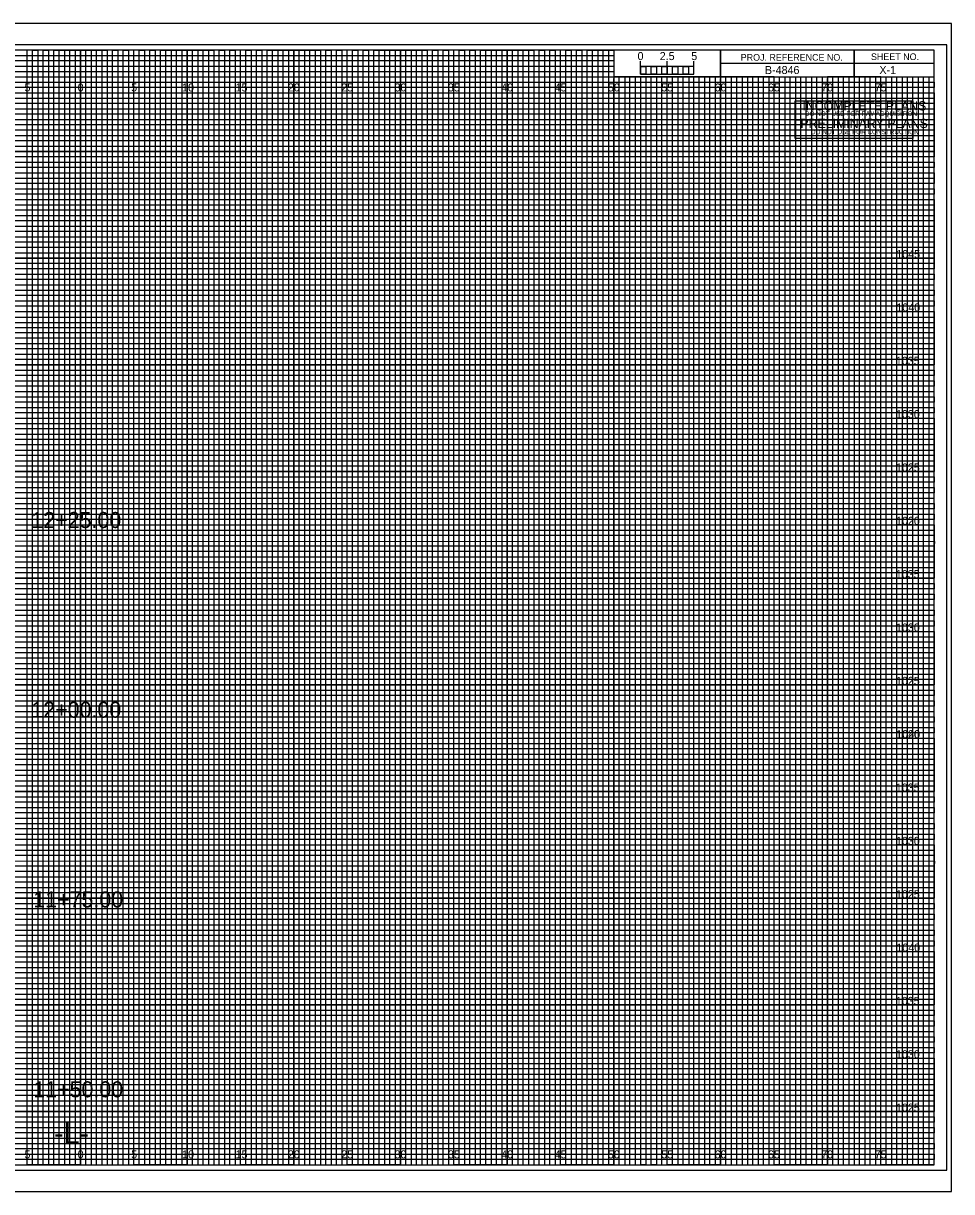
# Model space of a CAD drawing. Extents: x -7 to 162, y -2 to 987.
# Drawn here: x 74.6 to 161.7, y -2.5 to 107 of the extents above; entities that cross this region are included whole.
import ezdxf

# ---------------------------------------------------------------- set-up
doc = ezdxf.new("R2010")
doc.units = 0
for name, color, linetype in [('Default', 7, 'Continuous'), ('Exist Cross Section Cell', 7, 'Continuous'), ('Exist XS Center Line Elevation Label', 7, 'Continuous'), ('Exist XS Ground Line', 7, 'Continuous'), ('Prop CMT Concrete Structures', 7, 'Continuous'), ('Prop CMT DNC', 7, 'Continuous'), ('Prop CMT Guardrail Graphics', 7, 'Continuous'), ('Prop CMT Guardrail Widen Shoulder', 7, 'Continuous'), ('Prop CMT Pvmt Course 1', 7, 'Continuous'), ('Prop CMT Pvmt Surface', 7, 'Continuous'), ('Prop CMT Pvmt Surface Shoulder', 7, 'Continuous'), ('Prop CMT Shld Paved Course 1', 7, 'Continuous'), ('Prop CMT Shoulder Point', 7, 'Continuous'), ('Prop CMT Slope Grass', 7, 'Continuous'), ('Prop CMT Subgrade Earthwork', 7, 'Continuous'), ('Prop XS SE Text', 7, 'Continuous'), ('Prop XS Side Slope Text', 7, 'Continuous'), ('Typical Text Label CELL', 7, 'Continuous')]:
    doc.layers.add(name, color=color, linetype=linetype)

msp = doc.modelspace()

# ---------------------------------------------------------------- linework, layer by layer
at = {"layer": 'Default'}
for points in [[(146.99, 97.97), (146.99, 99.73), (158.01, 99.73), (158.01, 97.97)], [(146.99, 96.2), (146.99, 97.97), (158.01, 97.97), (158.01, 96.2)]]:
    msp.add_lwpolyline(points, close=True, dxfattribs=at)
at = {"layer": 'Exist XS Center Line Elevation Label'}
for points in [[(72.5, 0), (77.5, 0), (77.5, 104.5), (82.5, 104.5), (82.5, 0), (87.5, 0), (87.5, 104.5), (92.5, 104.5), (92.5, 0), (97.5, 0), (97.5, 104.5), (102.5, 104.5), (102.5, 0), (107.5, 0), (107.5, 104.5), (112.5, 104.5), (112.5, 0), (117.5, 0), (117.5, 104.5), (122.5, 104.5), (122.5, 0), (127.5, 0), (127.5, 104.5), (129.97, 104.5), (130, 104.5), (130, 102), (132.5, 102), (132.5, 0), (137.5, 0), (137.5, 102), (142.5, 102), (142.5, 0), (147.5, 0), (147.5, 102), (152.5, 102), (152.5, 0), (157.5, 0), (157.5, 102)], [(0, 102), (137.5, 102)], [(0, 92.5), (160, 92.5), (160, 97.5), (0, 97.5)], [(0, 82.5), (160, 82.5), (160, 87.5), (0, 87.5)], [(0, 72.5), (160, 72.5), (160, 77.5), (0, 77.5)], [(0, 62.5), (160, 62.5), (160, 67.5), (0, 67.5)], [(0, 52.5), (160, 52.5), (160, 57.5), (0, 57.5)], [(0, 42.5), (160, 42.5), (160, 47.5), (0, 47.5)], [(0, 32.5), (160, 32.5), (160, 37.5), (0, 37.5)], [(0, 22.5), (160, 22.5), (160, 27.5), (0, 27.5)], [(0, 12.5), (160, 12.5), (160, 17.5), (0, 17.5)], [(0, 2.5), (160, 2.5), (160, 7.5), (0, 7.5)]]:
    msp.add_lwpolyline(points, dxfattribs=at)
at = {"layer": 'Exist XS Ground Line'}
for p, q in [((75, 104.5), (70, 104.5)), ((75, 0), (75, 104.5)), ((85, 104.5), (80, 104.5)), ((80, 104.5), (80, 0)), ((85, 0), (85, 104.5)), ((95, 104.5), (90, 104.5)), ((90, 104.5), (90, 0)), ((95, 0), (95, 104.5)), ((105, 104.5), (100, 104.5)), ((100, 104.5), (100, 0)), ((105, 0), (105, 104.5)), ((115, 104.5), (110, 104.5)), ((110, 104.5), (110, 0)), ((115, 0), (115, 104.5)), ((125, 104.5), (120, 104.5)), ((120, 104.5), (120, 0)), ((125, 0), (125, 104.5)), ((130, 104.5), (130, 0)), ((135, 0), (135, 102)), ((145, 102), (140, 102)), ((140, 102), (140, 0)), ((145, 0), (145, 102)), ((155, 102), (150, 102)), ((150, 102), (150, 0)), ((155, 0), (155, 102)), ((80, 0), (75, 0)), ((90, 0), (85, 0)), ((100, 0), (95, 0)), ((110, 0), (105, 0)), ((120, 0), (115, 0)), ((130, 0), (125, 0)), ((140, 0), (135, 0)), ((150, 0), (145, 0)), ((160, 0), (155, 0)), ((160, 0), (160, 0))]:
    msp.add_line(p, q, dxfattribs=at)
for points in [[(0, 100), (160, 100), (160, 95), (0, 95)], [(0, 90), (160, 90), (160, 85), (0, 85)], [(0, 80), (160, 80), (160, 75), (0, 75)], [(0, 70), (160, 70), (160, 65), (0, 65)], [(0, 60), (160, 60), (160, 55), (0, 55)], [(0, 50), (160, 50), (160, 45), (0, 45)], [(0, 40), (160, 40), (160, 35), (0, 35)], [(0, 30), (160, 30), (160, 25), (0, 25)], [(0, 20), (160, 20), (160, 15), (0, 15)], [(0, 10), (160, 10), (160, 5), (0, 5)]]:
    msp.add_lwpolyline(points, dxfattribs=at)
at = {"layer": 'Prop CMT Concrete Structures'}
for p, q in [((75, 0), (75, 104.5)), ((80, 0), (80, 104.5)), ((85, 0), (85, 104.5)), ((90, 0), (90, 104.5)), ((95, 0), (95, 104.5)), ((100, 0), (100, 104.5)), ((105, 0), (105, 104.5)), ((110, 0), (110, 104.5)), ((115, 0), (115, 104.5)), ((120, 0), (120, 104.5)), ((125, 0), (125, 104.5)), ((130, 0), (130, 101.84)), ((135, 0), (135, 101.84)), ((140, 0), (140, 101.84)), ((145, 0), (145, 101.84)), ((150, 0), (150, 101.84)), ((155, 0), (155, 101.84)), ((0, 100), (160, 100)), ((0, 95), (160, 95)), ((0, 90), (160, 90)), ((0, 85), (160, 85)), ((0, 80), (160, 80)), ((0, 75), (160, 75)), ((0, 70), (160, 70)), ((0, 65), (160, 65)), ((0, 60), (160, 60)), ((0, 55), (160, 55)), ((0, 50), (160, 50)), ((0, 45), (160, 45)), ((0, 40), (160, 40)), ((0, 35), (160, 35)), ((0, 30), (160, 30)), ((0, 25), (160, 25)), ((0, 20), (160, 20)), ((0, 15), (160, 15)), ((0, 10), (160, 10)), ((0, 5), (160, 5))]:
    msp.add_line(p, q, dxfattribs=at)
at = {"layer": 'Prop CMT Guardrail Widen Shoulder'}
for p, q in [((161.65, 107), (-6.7, 107)), ((-6.7, -2.5), (161.65, -2.5))]:
    msp.add_line(p, q, dxfattribs=at)
at = {"layer": 'Prop CMT Pvmt Course 1'}
msp.add_lwpolyline([(-6.7, -2.5), (161.65, -2.5), (161.65, 107), (-6.7, 107)], close=True, dxfattribs=at)
at = {"layer": 'Prop CMT Pvmt Surface'}
for p, q in [((133.5, 102), (133, 102)), ((133, 102), (133, 0)), ((133.5, 0), (133.5, 102)), ((134.5, 102), (134, 102)), ((134, 102), (134, 0)), ((134.5, 0), (134.5, 102)), ((133, 0), (132.5, 0)), ((134, 0), (133.5, 0))]:
    msp.add_line(p, q, dxfattribs=at)
for points in [[(75, 0), (75.5, 0), (75.5, 104.5), (76, 104.5), (76, 0)], [(76, 0), (76.5, 0), (76.5, 104.5), (77, 104.5), (77, 0)], [(77.5, 0), (78, 0), (78, 104.5), (78.5, 104.5), (78.5, 0)], [(78.5, 0), (79, 0), (79, 104.5), (79.5, 104.5), (79.5, 0)], [(80, 0), (80.5, 0), (80.5, 104.5), (81, 104.5), (81, 0)], [(81, 0), (81.5, 0), (81.5, 104.5), (82, 104.5), (82, 0)], [(82.5, 0), (83, 0), (83, 104.5), (83.5, 104.5), (83.5, 0)], [(83.5, 0), (84, 0), (84, 104.5), (84.5, 104.5), (84.5, 0)], [(85, 0), (85.5, 0), (85.5, 104.5), (86, 104.5), (86, 0)], [(86, 0), (86.5, 0), (86.5, 104.5), (87, 104.5), (87, 0)], [(87.5, 0), (88, 0), (88, 104.5), (88.5, 104.5), (88.5, 0)], [(88.5, 0), (89, 0), (89, 104.5), (89.5, 104.5), (89.5, 0)], [(90, 0), (90.5, 0), (90.5, 104.5), (91, 104.5), (91, 0)], [(91, 0), (91.5, 0), (91.5, 104.5), (92, 104.5), (92, 0)], [(92.5, 0), (93, 0), (93, 104.5), (93.5, 104.5), (93.5, 0)], [(93.5, 0), (94, 0), (94, 104.5), (94.5, 104.5), (94.5, 0)], [(95, 0), (95.5, 0), (95.5, 104.5), (96, 104.5), (96, 0)], [(96, 0), (96.5, 0), (96.5, 104.5), (97, 104.5), (97, 0)], [(97.5, 0), (98, 0), (98, 104.5), (98.5, 104.5), (98.5, 0)], [(98.5, 0), (99, 0), (99, 104.5), (99.5, 104.5), (99.5, 0)], [(100, 0), (100.5, 0), (100.5, 104.5), (101, 104.5), (101, 0)], [(101, 0), (101.5, 0), (101.5, 104.5), (102, 104.5), (102, 0)], [(102.5, 0), (103, 0), (103, 104.5), (103.5, 104.5), (103.5, 0)], [(103.5, 0), (104, 0), (104, 104.5), (104.5, 104.5), (104.5, 0)], [(105, 0), (105.5, 0), (105.5, 104.5), (106, 104.5), (106, 0)], [(106, 0), (106.5, 0), (106.5, 104.5), (107, 104.5), (107, 0)], [(107.5, 0), (108, 0), (108, 104.5), (108.5, 104.5), (108.5, 0)], [(108.5, 0), (109, 0), (109, 104.5), (109.5, 104.5), (109.5, 0)], [(110, 0), (110.5, 0), (110.5, 104.5), (111, 104.5), (111, 0)], [(111, 0), (111.5, 0), (111.5, 104.5), (112, 104.5), (112, 0)], [(112.5, 0), (113, 0), (113, 104.5), (113.5, 104.5), (113.5, 0)], [(113.5, 0), (114, 0), (114, 104.5), (114.5, 104.5), (114.5, 0)], [(115, 0), (115.5, 0), (115.5, 104.5), (116, 104.5), (116, 0)], [(116, 0), (116.5, 0), (116.5, 104.5), (117, 104.5), (117, 0)], [(117.5, 0), (118, 0), (118, 104.5), (118.5, 104.5), (118.5, 0)], [(118.5, 0), (119, 0), (119, 104.5), (119.5, 104.5), (119.5, 0)], [(120, 0), (120.5, 0), (120.5, 104.5), (121, 104.5), (121, 0)], [(121, 0), (121.5, 0), (121.5, 104.5), (122, 104.5), (122, 0)], [(122.5, 0), (123, 0), (123, 104.5), (123.5, 104.5), (123.5, 0)], [(123.5, 0), (124, 0), (124, 104.5), (124.5, 104.5), (124.5, 0)], [(125, 0), (125.5, 0), (125.5, 104.5), (126, 104.5), (126, 0)], [(126, 0), (126.5, 0), (126.5, 104.5), (127, 104.5), (127, 0)], [(127.5, 0), (128, 0), (128, 104.5), (128.5, 104.5), (128.5, 0)], [(128.5, 0), (129, 0), (129, 104.5), (129.5, 104.5), (129.5, 0)], [(130, 0), (130.5, 0), (130.5, 102), (131.01, 102), (131.01, 0)], [(131, 0), (131.5, 0), (131.5, 102), (132, 102), (132, 0)], [(135, 0), (135.49, 0), (135.49, 102), (136, 102), (136, 0)], [(136, 0), (136.5, 0), (136.5, 102), (137.03, 102), (137.03, 0)], [(137.5, 0), (138, 0), (138, 102), (138.5, 102), (138.5, 0)], [(138.5, 0), (139, 0), (139, 102), (139.5, 102), (139.5, 0)], [(140, 0), (140.5, 0), (140.5, 102), (141, 102), (141, 0)], [(141, 0), (141.5, 0), (141.5, 102), (142, 102), (142, 0)], [(142.5, 0), (143, 0), (143, 102), (143.5, 102), (143.5, 0)], [(143.5, 0), (144, 0), (144, 102), (144.5, 102), (144.5, 0)], [(145, 0), (145.5, 0), (145.5, 102), (146, 102), (146, 0)], [(146, 0), (146.5, 0), (146.5, 102), (147, 102), (147, 0)], [(147.5, 0), (148, 0), (148, 102), (148.5, 102), (148.5, 0)], [(148.5, 0), (149, 0), (149, 102), (149.5, 102), (149.5, 0)], [(150, 0), (150.5, 0), (150.5, 102), (151, 102), (151, 0)], [(151, 0), (151.5, 0), (151.5, 102), (152, 102), (152, 0)], [(152.5, 0), (153, 0), (153, 102), (153.5, 102), (153.5, 0)], [(153.5, 0), (154, 0), (154, 102), (154.5, 102), (154.5, 0)], [(155, 0), (155.5, 0), (155.5, 102), (156, 102), (156, 0)], [(156, 0), (156.5, 0), (156.5, 102), (157, 102), (157, 0)], [(157.5, 0), (158, 0), (158, 102), (158.5, 102), (158.5, 0)], [(158.5, 0), (159, 0), (159, 102), (159.5, 102), (159.5, 0)]]:
    msp.add_lwpolyline(points, dxfattribs=at)
at = {"layer": 'Prop CMT Pvmt Surface Shoulder'}
for p, q in [((132.5, 102.25), (132.5, 103.45)), ((132.5, 102.95), (132.5, 103.45)), ((135, 102.25), (135, 103.45)), ((137.5, 102.25), (137.5, 103.45)), ((137.5, 102.95), (137.5, 103.45))]:
    msp.add_line(p, q, dxfattribs=at)
for points in [[(137.5, 102.95), (132.5, 102.95), (132.5, 102.25), (137.5, 102.25)], [(132.5, 102.95), (133, 102.95), (133, 102.25), (132.5, 102.25)], [(133.5, 102.95), (134, 102.95), (134, 102.25), (133.5, 102.25)], [(134.5, 102.95), (135, 102.95), (135, 102.25), (134.5, 102.25)], [(135.5, 102.95), (136, 102.95), (136, 102.25), (135.5, 102.25)], [(136.5, 102.95), (137, 102.95), (137, 102.25), (136.5, 102.25)]]:
    msp.add_lwpolyline(points, close=True, dxfattribs=at)
at = {"layer": 'Prop CMT Shld Paved Course 1'}
for p, q in [((0, 104), (130, 104)), ((130, 103.49), (0, 103.49)), ((0, 103), (130, 103)), ((130, 104), (130, 103.49)), ((130, 103), (130, 102.45)), ((130, 102.45), (0, 102.45)), ((0, 102), (160, 102))]:
    msp.add_line(p, q, dxfattribs=at)
for points in [[(0, 101.5), (135, 101.5), (160, 101.5), (160, 101), (0, 101)], [(0, 100.5), (160, 100.5), (160, 99.5), (0, 99.5)], [(0, 99), (160, 99), (160, 98.5), (0, 98.49)], [(0, 98), (160, 98), (160, 97), (0, 97)], [(0, 96.5), (160, 96.5), (160, 96), (0, 96)], [(0, 95.5), (160, 95.5), (160, 94.5), (0, 94.5)], [(0, 94), (160, 94), (160, 93.5), (0, 93.5)], [(0, 93), (160, 93), (160, 92), (0, 92)], [(0, 91.5), (160, 91.5), (160, 91), (0, 91)], [(0, 90.5), (160, 90.5), (160, 89.5), (0, 89.5)], [(0, 89), (160, 89), (160, 88.5), (0, 88.5)], [(0, 88), (160, 88), (160, 86.98), (160, 86.5), (160, 86), (0, 86)], [(0, 87), (160, 87), (160, 86.5), (0, 86.5)], [(0, 85.5), (160, 85.5), (160, 84.5), (0, 84.52)], [(0, 84.52), (160, 84.5), (160, 84), (0, 84)], [(0, 83.5), (160, 83.5), (160, 83), (0, 83)], [(0, 82), (160, 82), (160, 81.5), (0, 81.5)], [(0, 81), (160, 81), (160, 80.5), (0, 80.5)], [(-0.04, 79.45), (160, 79.45), (160, 78.94), (-0.04, 78.94)], [(0, 78.5), (160, 78.5), (160, 78), (0, 78)], [(0, 77), (160, 77), (160, 76.5), (0, 76.5)], [(0, 76), (160, 76), (160, 75.5), (0, 75.5)], [(0, 74.5), (160, 74.5), (160, 74), (0, 74)], [(0, 73.5), (160, 73.5), (160, 73), (0, 73)], [(0, 72), (160, 72), (160, 71.5), (0, 71.5)], [(0, 71), (160, 71), (160, 70.5), (0, 70.5)], [(0, 69.5), (160, 69.5), (160, 68.99), (0, 69)], [(0, 68.5), (160, 68.5), (160, 68), (0, 68)], [(0, 67), (160, 67), (160, 66.5), (0, 66.5)], [(0, 66), (160, 66), (160, 65.5), (0, 65.5)], [(0, 64.5), (160, 64.5), (160, 64), (0, 64)], [(0, 63.5), (160, 63.5), (160, 63), (0, 63)], [(0, 62), (160, 62), (160, 61.5), (0, 61.5)], [(0, 61), (160, 61), (160, 60.5), (0, 60.5)], [(0, 59.5), (160, 59.5), (160, 59), (0, 59)], [(0, 58.5), (160.03, 58.45), (160, 58), (0, 58)], [(0, 57), (160, 57), (160, 56.5), (0, 56.5)], [(0, 56), (160, 56), (160, 55.5), (0, 55.5)], [(0, 54.5), (160, 54.5), (160, 54), (0, 54)], [(0, 53.5), (160, 53.5), (160, 53), (0, 53)], [(0, 52), (160, 52), (160, 51.5), (0, 51.5)], [(0, 51), (160, 51), (160, 50.5), (0, 50.5)], [(0, 49.5), (160, 49.5), (160, 49), (0, 49)], [(0, 48.5), (160, 48.5), (160, 48), (0, 48)], [(0, 47), (160, 47), (160, 46.5), (0, 46.5)], [(0, 46), (160, 46), (160, 45.5), (0, 45.5)], [(0, 44.5), (160, 44.5), (160, 44), (0, 44)], [(0, 43.5), (160, 43.5), (160, 43), (0, 43)], [(0, 42), (160, 42), (160, 41.5), (0, 41.5)], [(0, 41), (160, 41), (160, 40.5), (0, 40.5)], [(0, 39.5), (160, 39.5), (160, 38.99), (0, 39)], [(0, 38.5), (160, 38.5), (160, 38), (0, 38)], [(0, 37), (160, 37), (160, 36.5), (0, 36.5)], [(0, 36), (160, 36), (160, 35.5), (0, 35.5)], [(0, 34.5), (160, 34.5), (160, 34), (0, 34)], [(0, 33.5), (160, 33.5), (160, 33), (0, 33)], [(0, 32), (160, 32), (160, 31.5), (0, 31.5)], [(0, 31), (160, 31), (160, 30.5), (0, 30.5)], [(0, 29.5), (160, 29.5), (160, 29), (0, 29)], [(0, 28.5), (160.03, 28.46), (160, 28), (0, 28)], [(0, 27), (160, 27), (160, 26.5), (0, 26.5)], [(0, 26), (160, 26), (160, 25.5), (0, 25.5)], [(0, 24.5), (160, 24.5), (160, 24), (0, 24)], [(0, 23.5), (160, 23.5), (160, 23), (0, 23)], [(0, 22), (160, 22), (160, 21.5), (0, 21.5)], [(0, 21), (160, 21), (160, 20.5), (0, 20.5)], [(0, 19.5), (160, 19.5), (160, 19), (0, 19)], [(0, 18.5), (160, 18.5), (160, 18), (0, 18)], [(0, 17), (160, 17), (160, 16.5), (0, 16.5)], [(0, 16), (160, 16), (160, 15.5), (0, 15.5)], [(0, 14.5), (160, 14.5), (160, 14), (0, 14)], [(0, 13.5), (160, 13.5), (160, 13), (0, 13)], [(0, 12), (160, 12), (160, 11.5), (0, 11.5)], [(0, 11), (160, 11), (160, 10.5), (0, 10.5)], [(0, 9.5), (160, 9.5), (160, 9), (0, 9)], [(0, 8.5), (160, 8.5), (160, 8), (0, 8)], [(0, 7), (160, 7), (160, 6.5), (0, 6.5)], [(0, 6), (160, 6), (160, 5.5), (0, 5.5)], [(0, 4.5), (160, 4.5), (160, 4), (0, 4)], [(0, 3.5), (160, 3.5), (160, 3), (0, 3)], [(0, 2), (160, 2), (160, 1.5), (0, 1.5)], [(0, 1), (160, 1), (160, 0.5), (0, 0.5)]]:
    msp.add_lwpolyline(points, dxfattribs=at)
at = {"layer": 'Prop CMT Slope Grass'}
msp.add_lwpolyline([(-5.4, -0.5), (161.2, -0.5), (161.2, 105), (-5.4, 105)], close=True, dxfattribs=at)
at = {"layer": 'Prop CMT Subgrade Earthwork'}
for p, q in [((152.5, 104.5), (152.5, 102)), ((152.5, 102), (152.5, 104.5)), ((160, 103.25), (140, 103.25)), ((140, 103.25), (140, 102)), ((140, 102), (160, 102))]:
    msp.add_line(p, q, dxfattribs=at)
for points in [[(160, 104.5), (0, 104.5), (0, 0), (160, 0)], [(140, 104.5), (130, 104.5), (130, 102.02), (140, 102.02)], [(160, 104.5), (140, 104.5), (140, 102), (160, 102)]]:
    msp.add_lwpolyline(points, close=True, dxfattribs=at)

# ---------------------------------------------------------------- texts
at = {"layer": 'Default'}
for s, height, p in [('INCOMPLETE PLANS', 0.864, (147.66, 98.84)), ('DO NOT USE FOR R/W ACQUISITION', 0.432, (147.9, 98.32)), ('PRELIMINARY PLANS', 0.864, (147.47, 97.19)), ('DO NOT USE FOR CONSTRUCTION', 0.432, (148.46, 96.61))]:
    msp.add_text(s, height=height, dxfattribs=at).set_placement(p)
at = {"layer": 'Exist Cross Section Cell'}
for s, p in [('5', (74.74, 100.62)), ('0', (79.73, 100.62)), ('0', (79.73, 100.62)), ('5', (84.74, 100.62)), ('10', (89.52, 100.62)), ('15', (94.53, 100.62)), ('20', (99.43, 100.62)), ('25', (104.44, 100.62)), ('30', (109.43, 100.62)), ('35', (114.44, 100.62)), ('40', (119.43, 100.62)), ('45', (124.44, 100.62)), ('50', (129.43, 100.62)), ('55', (134.44, 100.62)), ('60', (139.43, 100.62)), ('65', (144.44, 100.62)), ('70', (149.43, 100.62)), ('75', (154.44, 100.62)), ('5', (74.74, 0.62)), ('0', (79.73, 0.62)), ('0', (79.73, 0.62)), ('5', (84.74, 0.62)), ('10', (89.52, 0.62)), ('15', (94.53, 0.62)), ('20', (99.43, 0.62)), ('25', (104.44, 0.62)), ('30', (109.43, 0.62)), ('35', (114.44, 0.62)), ('40', (119.43, 0.62)), ('45', (124.44, 0.62)), ('50', (129.43, 0.62)), ('55', (134.44, 0.62)), ('60', (139.43, 0.62)), ('65', (144.44, 0.62)), ('70', (149.43, 0.62)), ('75', (154.44, 0.62))]:
    msp.add_text(s, height=0.75, dxfattribs=at).set_placement(p)
at = {"layer": 'Prop CMT DNC'}
msp.add_text('-L-', height=2, dxfattribs=at).set_placement((77.53, 2))
at = {"layer": 'Prop CMT Guardrail Graphics'}
msp.add_text('B-4846', height=0.75, dxfattribs=at).set_placement((144.15, 102.25))
at = {"layer": 'Prop CMT Pvmt Surface Shoulder'}
msp.add_text('0', height=0.75, dxfattribs=at).set_placement((132.21, 103.56))
at = {"layer": 'Prop CMT Shoulder Point'}
for s, p in [('2.5', (134.29, 103.56)), ('5', (137.24, 103.56))]:
    msp.add_text(s, height=0.75, dxfattribs=at).set_placement(p)
at = {"layer": 'Prop CMT Subgrade Earthwork'}
for s, p in [('PROJ. REFERENCE NO.', (141.88, 103.5)), ('SHEET NO.', (154.09, 103.56))]:
    msp.add_text(s, height=0.625, dxfattribs=at).set_placement(p)
at = {"layer": 'Prop XS SE Text'}
msp.add_text('X-1', height=0.75, dxfattribs=at).set_placement((154.88, 102.25))
at = {"layer": 'Prop XS Side Slope Text'}
for s, p in [('12+25.00', (75.39, 59.7)), ('12+00.00', (75.39, 41.92)), ('11+75.00', (75.57, 24.14)), ('11+50.00', (75.57, 6.34))]:
    msp.add_text(s, height=1.5, dxfattribs=at).set_placement(p)
at = {"layer": 'Typical Text Label CELL'}
for s, p in [('1045', (156.46, 85)), ('1040', (156.47, 80)), ('1035', (156.42, 75)), ('1030', (156.43, 70)), ('1025', (156.43, 65)), ('1020', (156.44, 60)), ('1035', (156.42, 55)), ('1030', (156.43, 50)), ('1025', (156.43, 45)), ('1020', (156.44, 40)), ('1040', (156.47, 40)), ('1035', (156.42, 35)), ('1030', (156.43, 30)), ('1025', (156.43, 25)), ('1040', (156.47, 20)), ('1035', (156.42, 15)), ('1030', (156.43, 10)), ('1025', (156.43, 5))]:
    msp.add_text(s, height=0.75, dxfattribs=at).set_placement(p)

doc.saveas('drawing.dxf')
